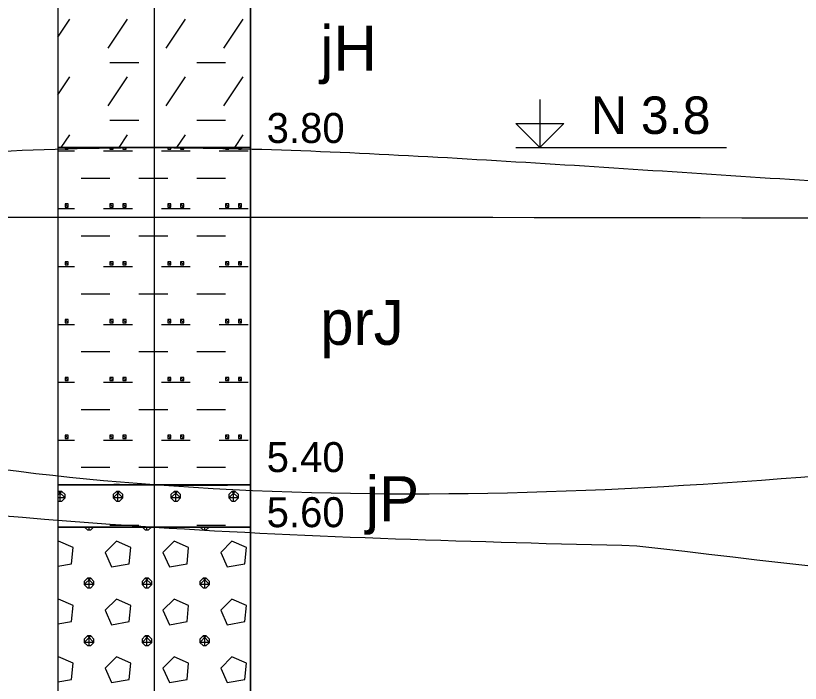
# Model space of a CAD drawing. Extents: x 3042 to 4120, y 576 to 2694.
# Drawn here: x 3373.31 to 3391.93, y 1581.88 to 1597.71 of the extents above; entities that cross this region are included whole.
import ezdxf

# ---------------------------------------------------------------- set-up
doc = ezdxf.new("R2010")
doc.units = 0
for name, color, linetype in [('51', 7, 'Continuous'), ('52', 7, 'Continuous'), ('53', 7, 'Continuous'), ('56', 7, 'Continuous'), ('61', 7, 'Continuous'), ('HPV', 7, 'Continuous'), ('pomocna', 7, 'Continuous'), ('rozhraní', 7, 'Continuous')]:
    doc.layers.add(name, color=color, linetype=linetype)

msp = doc.modelspace()

# ---------------------------------------------------------------- linework, layer by layer
at = {"layer": '51'}
for points in [[(3374.313, 1594.586), (3378.885, 1594.586), (3378.885, 1599.586), (3374.313, 1599.586)], [(3374.313, 1586.586), (3378.885, 1586.586), (3378.885, 1594.586), (3374.313, 1594.586)], [(3374.313, 1585.586), (3378.885, 1585.586), (3378.885, 1586.586), (3374.313, 1586.586)], [(3374.313, 1571.586), (3378.885, 1571.586), (3378.885, 1585.586), (3374.313, 1585.586)]]:
    msp.add_lwpolyline(points, close=True, dxfattribs=at)
for points in [[(3374.313, 1597.209), (3374.596, 1597.633)], [(3375.51, 1596.948), (3375.968, 1597.633)], [(3376.882, 1596.948), (3377.339, 1597.633)], [(3378.254, 1596.948), (3378.711, 1597.633)], [(3375.549, 1596.605), (3376.234, 1596.605)], [(3377.606, 1596.605), (3378.292, 1596.605)], [(3374.313, 1595.838), (3374.596, 1596.262)], [(3375.51, 1595.576), (3375.968, 1596.262)], [(3376.882, 1595.576), (3377.339, 1596.262)], [(3378.254, 1595.576), (3378.711, 1596.262)], [(3375.549, 1595.233), (3376.234, 1595.233)], [(3377.606, 1595.233), (3378.292, 1595.233)], [(3374.393, 1594.586), (3374.596, 1594.89)], [(3375.765, 1594.586), (3375.968, 1594.89)], [(3377.136, 1594.586), (3377.339, 1594.89)], [(3378.508, 1594.586), (3378.711, 1594.89)], [(3374.482, 1594.586), (3374.482, 1594.547), (3374.558, 1594.547), (3374.558, 1594.586)], [(3374.519, 1594.586), (3374.558, 1594.547)], [(3375.549, 1594.586), (3375.549, 1594.547), (3375.625, 1594.547), (3375.625, 1594.586)], [(3375.586, 1594.586), (3375.625, 1594.547)], [(3375.853, 1594.586), (3375.853, 1594.547), (3375.93, 1594.547), (3375.93, 1594.586)], [(3375.891, 1594.586), (3375.93, 1594.547)], [(3376.92, 1594.586), (3376.92, 1594.547), (3376.996, 1594.547), (3376.996, 1594.586)], [(3376.958, 1594.586), (3376.996, 1594.547)], [(3377.225, 1594.586), (3377.225, 1594.547), (3377.301, 1594.547), (3377.301, 1594.586)], [(3377.263, 1594.586), (3377.301, 1594.547)], [(3378.292, 1594.586), (3378.292, 1594.547), (3378.368, 1594.547), (3378.368, 1594.586)], [(3378.329, 1594.586), (3378.368, 1594.547)], [(3378.597, 1594.586), (3378.597, 1594.547), (3378.673, 1594.547), (3378.673, 1594.586)], [(3378.634, 1594.586), (3378.673, 1594.547)], [(3374.313, 1594.509), (3374.71, 1594.509)], [(3375.396, 1594.509), (3376.082, 1594.509)], [(3376.768, 1594.509), (3377.454, 1594.509)], [(3378.139, 1594.509), (3378.825, 1594.509)], [(3374.863, 1593.861), (3375.549, 1593.861)], [(3376.234, 1593.861), (3376.92, 1593.861)], [(3377.606, 1593.861), (3378.292, 1593.861)], [(3374.482, 1593.252), (3374.482, 1593.176), (3374.558, 1593.176), (3374.558, 1593.252), (3374.482, 1593.252), (3374.558, 1593.176)], [(3375.549, 1593.252), (3375.549, 1593.176), (3375.625, 1593.176), (3375.625, 1593.252), (3375.549, 1593.252), (3375.625, 1593.176)], [(3375.853, 1593.252), (3375.853, 1593.176), (3375.93, 1593.176), (3375.93, 1593.252), (3375.853, 1593.252), (3375.93, 1593.176)], [(3376.92, 1593.252), (3376.92, 1593.176), (3376.996, 1593.176), (3376.996, 1593.252), (3376.92, 1593.252), (3376.996, 1593.176)], [(3377.225, 1593.252), (3377.225, 1593.176), (3377.301, 1593.176), (3377.301, 1593.252), (3377.225, 1593.252), (3377.301, 1593.176)], [(3378.292, 1593.252), (3378.292, 1593.176), (3378.368, 1593.176), (3378.368, 1593.252), (3378.292, 1593.252), (3378.368, 1593.176)], [(3378.597, 1593.252), (3378.597, 1593.176), (3378.673, 1593.176), (3378.673, 1593.252), (3378.597, 1593.252), (3378.673, 1593.176)], [(3374.313, 1593.138), (3374.71, 1593.138)], [(3375.396, 1593.138), (3376.082, 1593.138)], [(3376.768, 1593.138), (3377.454, 1593.138)], [(3378.139, 1593.138), (3378.825, 1593.138)], [(3374.863, 1592.49), (3375.549, 1592.49)], [(3376.234, 1592.49), (3376.92, 1592.49)], [(3377.606, 1592.49), (3378.292, 1592.49)], [(3374.313, 1591.766), (3374.71, 1591.766)], [(3374.482, 1591.88), (3374.482, 1591.804), (3374.558, 1591.804), (3374.558, 1591.88), (3374.482, 1591.88), (3374.558, 1591.804)], [(3375.396, 1591.766), (3376.082, 1591.766)], [(3375.549, 1591.88), (3375.549, 1591.804), (3375.625, 1591.804), (3375.625, 1591.88), (3375.549, 1591.88), (3375.625, 1591.804)], [(3375.853, 1591.88), (3375.853, 1591.804), (3375.93, 1591.804), (3375.93, 1591.88), (3375.853, 1591.88), (3375.93, 1591.804)], [(3376.768, 1591.766), (3377.454, 1591.766)], [(3376.92, 1591.88), (3376.92, 1591.804), (3376.996, 1591.804), (3376.996, 1591.88), (3376.92, 1591.88), (3376.996, 1591.804)], [(3377.225, 1591.88), (3377.225, 1591.804), (3377.301, 1591.804), (3377.301, 1591.88), (3377.225, 1591.88), (3377.301, 1591.804)], [(3378.139, 1591.766), (3378.825, 1591.766)], [(3378.292, 1591.88), (3378.292, 1591.804), (3378.368, 1591.804), (3378.368, 1591.88), (3378.292, 1591.88), (3378.368, 1591.804)], [(3378.597, 1591.88), (3378.597, 1591.804), (3378.673, 1591.804), (3378.673, 1591.88), (3378.597, 1591.88), (3378.673, 1591.804)], [(3374.863, 1591.118), (3375.549, 1591.118)], [(3376.234, 1591.118), (3376.92, 1591.118)], [(3377.606, 1591.118), (3378.292, 1591.118)], [(3374.482, 1590.509), (3374.482, 1590.432), (3374.558, 1590.432), (3374.558, 1590.509), (3374.482, 1590.509), (3374.558, 1590.432)], [(3375.549, 1590.509), (3375.549, 1590.432), (3375.625, 1590.432), (3375.625, 1590.509), (3375.549, 1590.509), (3375.625, 1590.432)], [(3375.853, 1590.509), (3375.853, 1590.432), (3375.93, 1590.432), (3375.93, 1590.509), (3375.853, 1590.509), (3375.93, 1590.432)], [(3376.92, 1590.509), (3376.92, 1590.432), (3376.996, 1590.432), (3376.996, 1590.509), (3376.92, 1590.509), (3376.996, 1590.432)], [(3377.225, 1590.509), (3377.225, 1590.432), (3377.301, 1590.432), (3377.301, 1590.509), (3377.225, 1590.509), (3377.301, 1590.432)], [(3378.292, 1590.509), (3378.292, 1590.432), (3378.368, 1590.432), (3378.368, 1590.509), (3378.292, 1590.509), (3378.368, 1590.432)], [(3378.597, 1590.509), (3378.597, 1590.432), (3378.673, 1590.432), (3378.673, 1590.509), (3378.597, 1590.509), (3378.673, 1590.432)], [(3374.313, 1590.394), (3374.71, 1590.394)], [(3375.396, 1590.394), (3376.082, 1590.394)], [(3376.768, 1590.394), (3377.454, 1590.394)], [(3378.139, 1590.394), (3378.825, 1590.394)], [(3374.863, 1589.747), (3375.549, 1589.747)], [(3376.234, 1589.747), (3376.92, 1589.747)], [(3377.606, 1589.747), (3378.292, 1589.747)], [(3374.313, 1589.023), (3374.71, 1589.023)], [(3374.482, 1589.137), (3374.482, 1589.061), (3374.558, 1589.061), (3374.558, 1589.137), (3374.482, 1589.137), (3374.558, 1589.061)], [(3375.396, 1589.023), (3376.082, 1589.023)], [(3375.549, 1589.137), (3375.549, 1589.061), (3375.625, 1589.061), (3375.625, 1589.137), (3375.549, 1589.137), (3375.625, 1589.061)], [(3375.853, 1589.137), (3375.853, 1589.061), (3375.93, 1589.061), (3375.93, 1589.137), (3375.853, 1589.137), (3375.93, 1589.061)], [(3376.768, 1589.023), (3377.454, 1589.023)], [(3376.92, 1589.137), (3376.92, 1589.061), (3376.996, 1589.061), (3376.996, 1589.137), (3376.92, 1589.137), (3376.996, 1589.061)], [(3377.225, 1589.137), (3377.225, 1589.061), (3377.301, 1589.061), (3377.301, 1589.137), (3377.225, 1589.137), (3377.301, 1589.061)], [(3378.139, 1589.023), (3378.825, 1589.023)], [(3378.292, 1589.137), (3378.292, 1589.061), (3378.368, 1589.061), (3378.368, 1589.137), (3378.292, 1589.137), (3378.368, 1589.061)], [(3378.597, 1589.137), (3378.597, 1589.061), (3378.673, 1589.061), (3378.673, 1589.137), (3378.597, 1589.137), (3378.673, 1589.061)], [(3374.863, 1588.375), (3375.549, 1588.375)], [(3376.234, 1588.375), (3376.92, 1588.375)], [(3377.606, 1588.375), (3378.292, 1588.375)], [(3374.482, 1587.765), (3374.482, 1587.689), (3374.558, 1587.689), (3374.558, 1587.765), (3374.482, 1587.765), (3374.558, 1587.689)], [(3375.549, 1587.765), (3375.549, 1587.689), (3375.625, 1587.689), (3375.625, 1587.765), (3375.549, 1587.765), (3375.625, 1587.689)], [(3375.853, 1587.765), (3375.853, 1587.689), (3375.93, 1587.689), (3375.93, 1587.765), (3375.853, 1587.765), (3375.93, 1587.689)], [(3376.92, 1587.765), (3376.92, 1587.689), (3376.996, 1587.689), (3376.996, 1587.765), (3376.92, 1587.765), (3376.996, 1587.689)], [(3377.225, 1587.765), (3377.225, 1587.689), (3377.301, 1587.689), (3377.301, 1587.765), (3377.225, 1587.765), (3377.301, 1587.689)], [(3378.292, 1587.765), (3378.292, 1587.689), (3378.368, 1587.689), (3378.368, 1587.765), (3378.292, 1587.765), (3378.368, 1587.689)], [(3378.597, 1587.765), (3378.597, 1587.689), (3378.673, 1587.689), (3378.673, 1587.765), (3378.597, 1587.765), (3378.673, 1587.689)], [(3374.313, 1587.651), (3374.71, 1587.651)], [(3375.396, 1587.651), (3376.082, 1587.651)], [(3376.768, 1587.651), (3377.454, 1587.651)], [(3378.139, 1587.651), (3378.825, 1587.651)], [(3374.863, 1587.003), (3375.549, 1587.003)], [(3376.234, 1587.003), (3376.92, 1587.003)], [(3377.606, 1587.003), (3378.292, 1587.003)], [(3374.329, 1586.432), (3374.313, 1586.416)], [(3374.313, 1586.219), (3374.329, 1586.203), (3374.406, 1586.203), (3374.482, 1586.28), (3374.482, 1586.356), (3374.406, 1586.432), (3374.329, 1586.432), (3374.482, 1586.28), (3374.313, 1586.28)], [(3374.313, 1586.34), (3374.406, 1586.432)], [(3374.367, 1586.203), (3374.367, 1586.432)], [(3375.701, 1586.432), (3375.625, 1586.356), (3375.625, 1586.28), (3375.701, 1586.203), (3375.777, 1586.203), (3375.853, 1586.28), (3375.853, 1586.356), (3375.777, 1586.432), (3375.701, 1586.432), (3375.853, 1586.28), (3375.625, 1586.28), (3375.777, 1586.432)], [(3375.739, 1586.203), (3375.739, 1586.432)], [(3377.073, 1586.432), (3376.996, 1586.356), (3376.996, 1586.28), (3377.073, 1586.203), (3377.149, 1586.203), (3377.225, 1586.28), (3377.225, 1586.356), (3377.149, 1586.432), (3377.073, 1586.432), (3377.225, 1586.28), (3376.996, 1586.28), (3377.149, 1586.432)], [(3377.111, 1586.203), (3377.111, 1586.432)], [(3378.444, 1586.432), (3378.368, 1586.356), (3378.368, 1586.28), (3378.444, 1586.203), (3378.52, 1586.203), (3378.597, 1586.28), (3378.597, 1586.356), (3378.52, 1586.432), (3378.444, 1586.432), (3378.597, 1586.28), (3378.368, 1586.28), (3378.52, 1586.432)], [(3378.482, 1586.203), (3378.482, 1586.432)], [(3375.549, 1585.632), (3376.234, 1585.632)], [(3377.606, 1585.632), (3378.292, 1585.632)], [(3374.947, 1585.586), (3375.015, 1585.518), (3375.091, 1585.518), (3375.16, 1585.586)], [(3375.053, 1585.518), (3375.053, 1585.586)], [(3376.318, 1585.586), (3376.387, 1585.518), (3376.463, 1585.518), (3376.531, 1585.586)], [(3376.425, 1585.518), (3376.425, 1585.586)], [(3377.69, 1585.586), (3377.758, 1585.518), (3377.835, 1585.518), (3377.903, 1585.586)], [(3377.796, 1585.518), (3377.796, 1585.586)], [(3374.313, 1584.659), (3374.634, 1584.717), (3374.672, 1585.098), (3374.329, 1585.251), (3374.313, 1585.235)], [(3375.434, 1584.984), (3375.587, 1584.641), (3376.006, 1584.717), (3376.044, 1585.098), (3375.701, 1585.251), (3375.434, 1584.984)], [(3376.806, 1584.984), (3376.958, 1584.641), (3377.377, 1584.717), (3377.415, 1585.098), (3377.073, 1585.251), (3376.806, 1584.984)], [(3378.177, 1584.984), (3378.33, 1584.641), (3378.749, 1584.717), (3378.787, 1585.098), (3378.444, 1585.251), (3378.177, 1584.984)], [(3375.015, 1584.375), (3374.939, 1584.298), (3374.939, 1584.222), (3375.015, 1584.146), (3375.091, 1584.146), (3375.168, 1584.222), (3375.168, 1584.298), (3375.091, 1584.375), (3375.015, 1584.375), (3375.168, 1584.222), (3374.939, 1584.222), (3375.091, 1584.375)], [(3375.053, 1584.146), (3375.053, 1584.375)], [(3376.387, 1584.375), (3376.311, 1584.298), (3376.311, 1584.222), (3376.387, 1584.146), (3376.463, 1584.146), (3376.539, 1584.222), (3376.539, 1584.298), (3376.463, 1584.375), (3376.387, 1584.375), (3376.539, 1584.222), (3376.311, 1584.222), (3376.463, 1584.375)], [(3376.425, 1584.146), (3376.425, 1584.375)], [(3377.758, 1584.375), (3377.682, 1584.298), (3377.682, 1584.222), (3377.758, 1584.146), (3377.835, 1584.146), (3377.911, 1584.222), (3377.911, 1584.298), (3377.835, 1584.375), (3377.758, 1584.375), (3377.911, 1584.222), (3377.682, 1584.222), (3377.835, 1584.375)], [(3377.796, 1584.146), (3377.796, 1584.375)], [(3374.313, 1583.288), (3374.634, 1583.346), (3374.672, 1583.727), (3374.329, 1583.879), (3374.313, 1583.863)], [(3375.434, 1583.613), (3375.587, 1583.27), (3376.006, 1583.346), (3376.044, 1583.727), (3375.701, 1583.879), (3375.434, 1583.613)], [(3376.806, 1583.613), (3376.958, 1583.27), (3377.377, 1583.346), (3377.415, 1583.727), (3377.073, 1583.879), (3376.806, 1583.613)], [(3378.177, 1583.613), (3378.33, 1583.27), (3378.749, 1583.346), (3378.787, 1583.727), (3378.444, 1583.879), (3378.177, 1583.613)], [(3375.015, 1583.003), (3374.939, 1582.927), (3374.939, 1582.851), (3375.015, 1582.774), (3375.091, 1582.774), (3375.168, 1582.851), (3375.168, 1582.927), (3375.091, 1583.003), (3375.015, 1583.003), (3375.168, 1582.851), (3374.939, 1582.851), (3375.091, 1583.003)], [(3375.053, 1582.774), (3375.053, 1583.003)], [(3376.387, 1583.003), (3376.311, 1582.927), (3376.311, 1582.851), (3376.387, 1582.774), (3376.463, 1582.774), (3376.539, 1582.851), (3376.539, 1582.927), (3376.463, 1583.003), (3376.387, 1583.003), (3376.539, 1582.851), (3376.311, 1582.851), (3376.463, 1583.003)], [(3376.425, 1582.774), (3376.425, 1583.003)], [(3377.758, 1583.003), (3377.682, 1582.927), (3377.682, 1582.851), (3377.758, 1582.774), (3377.835, 1582.774), (3377.911, 1582.851), (3377.911, 1582.927), (3377.835, 1583.003), (3377.758, 1583.003), (3377.911, 1582.851), (3377.682, 1582.851), (3377.835, 1583.003)], [(3377.796, 1582.774), (3377.796, 1583.003)], [(3374.313, 1581.916), (3374.634, 1581.974), (3374.672, 1582.355), (3374.329, 1582.508), (3374.313, 1582.492)], [(3375.434, 1582.241), (3375.587, 1581.898), (3376.006, 1581.974), (3376.044, 1582.355), (3375.701, 1582.508), (3375.434, 1582.241)], [(3376.806, 1582.241), (3376.958, 1581.898), (3377.377, 1581.974), (3377.415, 1582.355), (3377.073, 1582.508), (3376.806, 1582.241)], [(3378.177, 1582.241), (3378.33, 1581.898), (3378.749, 1581.974), (3378.787, 1582.355), (3378.444, 1582.508), (3378.177, 1582.241)]]:
    msp.add_lwpolyline(points, dxfattribs=at)
at = {"layer": '53'}
for points in [[(3374.313, 1613.586), (3374.313, 1568.586)], [(3378.885, 1613.586), (3378.885, 1568.586)], [(3374.313, 1594.586), (3378.885, 1594.586)], [(3374.313, 1586.586), (3378.885, 1586.586)], [(3374.313, 1585.586), (3378.885, 1585.586)]]:
    msp.add_lwpolyline(points, dxfattribs=at)
at = {"layer": '56'}
for points in [[(3376.599, 1594.967), (3376.599, 1594.205)], [(3376.218, 1594.586), (3376.98, 1594.586)], [(3376.599, 1586.967), (3376.599, 1586.205)], [(3376.218, 1586.586), (3376.98, 1586.586)], [(3376.599, 1585.967), (3376.599, 1585.205)], [(3376.218, 1585.586), (3376.98, 1585.586)]]:
    msp.add_lwpolyline(points, dxfattribs=at)
at = {"layer": '61'}
for points in [[(3385.748, 1595.729), (3385.748, 1594.586), (3385.177, 1595.157), (3386.32, 1595.157), (3385.748, 1594.586)], [(3385.177, 1594.586), (3390.172, 1594.586)]]:
    msp.add_lwpolyline(points, dxfattribs=at)
at = {"layer": 'HPV'}
msp.add_spline([(3258.558, 1595.438), (3265.132, 1595.438), (3304.222, 1591.874), (3343.272, 1592.467), (3406.282, 1592.961), (3505.772, 1594.985), (3516.554, 1594.985)], degree=3, dxfattribs=at)
at = {"layer": 'pomocna'}
msp.add_line((3376.602, 1551.838), (3376.602, 1611.375), dxfattribs=at)
at = {"layer": 'rozhraní'}
for points in [[(3343.149, 1592.908), (3343.272, 1592.888), (3351.552, 1592.438), (3359.888, 1593.128), (3368.248, 1594.122), (3372.427, 1594.472), (3376.599, 1594.586), (3384.02, 1594.321), (3391.441, 1593.85), (3398.862, 1593.447), (3406.282, 1593.388), (3418.367, 1594.021), (3430.442, 1595.004), (3442.519, 1595.967), (3454.612, 1596.538), (3467.4, 1596.805), (3480.19, 1597.046), (3505.772, 1597.288), (3515.471, 1597.288)], [(3514.887, 1589.833), (3505.845, 1589.635), (3454.612, 1592.538), (3406.282, 1588.388), (3376.599, 1586.586), (3364.06, 1589.145), (3356.751, 1592.851)], [(3258.853, 1591.438), (3265.132, 1591.438), (3304.222, 1584.538), (3343.272, 1587.888), (3376.599, 1585.586), (3388.049, 1585.144)], [(3388.049, 1585.144), (3406.282, 1583.388), (3454.612, 1585.538), (3505.772, 1587.788), (3517.156, 1587.788)], [(3375.64, 1586.603), (3376.706, 1586.586), (3378.885, 1586.586)]]:
    msp.add_spline(points, degree=3, dxfattribs=at)

# ---------------------------------------------------------------- texts
at = {"layer": '52'}
for s, height, p in [('jH', 1.0668, (3380.536, 1596.408)), ('3.80', 0.7112, (3379.266, 1594.696)), ('prJ', 1.0668, (3380.536, 1589.908)), ('5.40', 0.7112, (3379.266, 1586.89)), ('jP', 1.0668, (3381.616, 1585.725)), ('5.60', 0.7112, (3379.266, 1585.583))]:
    msp.add_text(s, height=height, dxfattribs=at).set_placement(p)
at = {"layer": '61'}
msp.add_text('N 3.8', height=0.889, dxfattribs=at).set_placement((3386.955, 1594.91))

doc.saveas('drawing.dxf')
